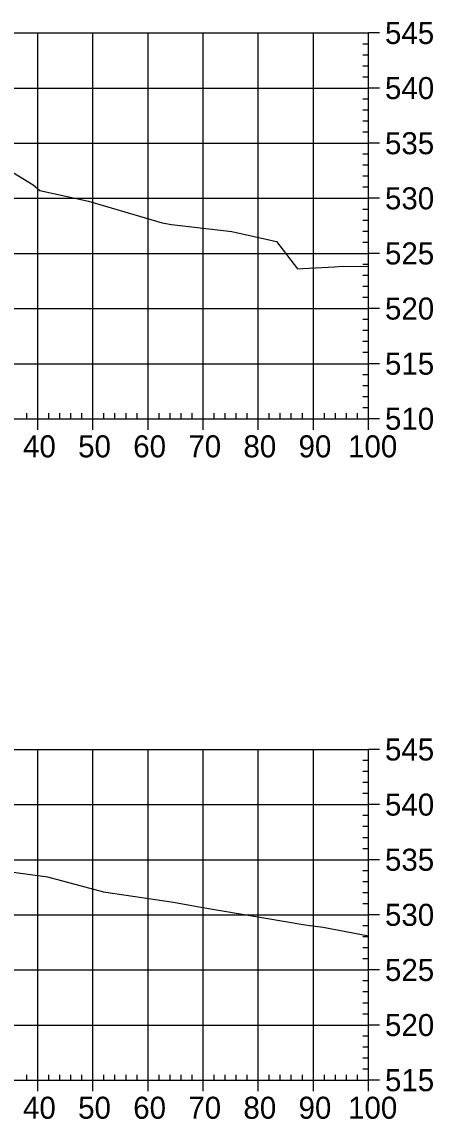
# Model space of a CAD drawing. Extents: x 704834 to 709892, y 372981 to 377533.
# Drawn here: x 707342 to 707416.6, y 376473.8 to 376672.8 of the extents above; entities that cross this region are included whole.
import ezdxf

# ---------------------------------------------------------------- set-up
doc = ezdxf.new("R2010")
doc.units = 0
doc.layers.add('57', color=7, linetype='Continuous')
doc.layers.add('Existing', color=7, linetype='Continuous')

msp = doc.modelspace()

# ---------------------------------------------------------------- linework, layer by layer
at = {"layer": '57'}
for p, q in [((707204.91, 376670.82), (707404.91, 376670.82)), ((707344.91, 376600.82), (707344.91, 376670.82)), ((707354.91, 376600.82), (707354.91, 376670.82)), ((707364.91, 376600.82), (707364.91, 376670.82)), ((707374.91, 376600.82), (707374.91, 376670.82)), ((707384.91, 376600.82), (707384.91, 376670.82)), ((707394.91, 376600.82), (707394.91, 376670.82)), ((707404.91, 376600.82), (707404.91, 376670.82)), ((707404.91, 376600.82), (707404.91, 376670.82)), ((707406.91, 376670.82), (707404.91, 376670.82)), ((707404.91, 376668.82), (707403.91, 376668.82)), ((707404.91, 376666.82), (707403.91, 376666.82)), ((707404.91, 376664.82), (707403.91, 376664.82)), ((707404.91, 376662.82), (707403.91, 376662.82)), ((707204.91, 376660.82), (707404.91, 376660.82)), ((707406.91, 376660.82), (707404.91, 376660.82)), ((707404.91, 376658.82), (707403.91, 376658.82)), ((707404.91, 376656.82), (707403.91, 376656.82)), ((707404.91, 376654.82), (707403.91, 376654.82)), ((707404.91, 376652.82), (707403.91, 376652.82)), ((707204.91, 376650.82), (707404.91, 376650.82)), ((707406.91, 376650.82), (707404.91, 376650.82)), ((707404.91, 376648.82), (707403.91, 376648.82)), ((707404.91, 376646.82), (707403.91, 376646.82)), ((707404.91, 376644.82), (707403.91, 376644.82)), ((707404.91, 376642.82), (707403.91, 376642.82)), ((707204.91, 376640.82), (707404.91, 376640.82)), ((707406.91, 376640.82), (707404.91, 376640.82)), ((707404.91, 376638.82), (707403.91, 376638.82)), ((707404.91, 376636.82), (707403.91, 376636.82)), ((707404.91, 376634.82), (707403.91, 376634.82)), ((707404.91, 376632.82), (707403.91, 376632.82)), ((707204.91, 376630.82), (707404.91, 376630.82)), ((707406.91, 376630.82), (707404.91, 376630.82)), ((707404.91, 376628.82), (707403.91, 376628.82)), ((707404.91, 376626.82), (707403.91, 376626.82)), ((707404.91, 376624.82), (707403.91, 376624.82)), ((707404.91, 376622.82), (707403.91, 376622.82)), ((707204.91, 376620.82), (707404.91, 376620.82)), ((707406.91, 376620.82), (707404.91, 376620.82)), ((707404.91, 376618.82), (707403.91, 376618.82)), ((707404.91, 376616.82), (707403.91, 376616.82)), ((707404.91, 376614.82), (707403.91, 376614.82)), ((707404.91, 376612.82), (707403.91, 376612.82)), ((707204.91, 376610.82), (707404.91, 376610.82)), ((707406.91, 376610.82), (707404.91, 376610.82)), ((707404.91, 376608.82), (707403.91, 376608.82)), ((707404.91, 376606.82), (707403.91, 376606.82)), ((707404.91, 376604.82), (707403.91, 376604.82)), ((707342.91, 376600.82), (707342.91, 376601.82)), ((707346.91, 376600.82), (707346.91, 376601.82)), ((707348.91, 376600.82), (707348.91, 376601.82)), ((707350.91, 376600.82), (707350.91, 376601.82)), ((707352.91, 376600.82), (707352.91, 376601.82)), ((707356.91, 376600.82), (707356.91, 376601.82)), ((707358.91, 376600.82), (707358.91, 376601.82)), ((707360.91, 376600.82), (707360.91, 376601.82)), ((707362.91, 376600.82), (707362.91, 376601.82)), ((707366.91, 376600.82), (707366.91, 376601.82)), ((707368.91, 376600.82), (707368.91, 376601.82)), ((707370.91, 376600.82), (707370.91, 376601.82)), ((707372.91, 376600.82), (707372.91, 376601.82)), ((707376.91, 376600.82), (707376.91, 376601.82)), ((707378.91, 376600.82), (707378.91, 376601.82)), ((707380.91, 376600.82), (707380.91, 376601.82)), ((707382.91, 376600.82), (707382.91, 376601.82)), ((707386.91, 376600.82), (707386.91, 376601.82)), ((707388.91, 376600.82), (707388.91, 376601.82)), ((707390.91, 376600.82), (707390.91, 376601.82)), ((707392.91, 376600.82), (707392.91, 376601.82)), ((707396.91, 376600.82), (707396.91, 376601.82)), ((707398.91, 376600.82), (707398.91, 376601.82)), ((707400.91, 376600.82), (707400.91, 376601.82)), ((707402.91, 376600.82), (707402.91, 376601.82)), ((707404.91, 376602.82), (707403.91, 376602.82)), ((707204.91, 376600.82), (707404.91, 376600.82)), ((707204.91, 376600.82), (707404.91, 376600.82)), ((707344.91, 376598.82), (707344.91, 376600.82)), ((707354.91, 376598.82), (707354.91, 376600.82)), ((707364.91, 376598.82), (707364.91, 376600.82)), ((707374.91, 376598.82), (707374.91, 376600.82)), ((707384.91, 376598.82), (707384.91, 376600.82)), ((707394.91, 376598.82), (707394.91, 376600.82)), ((707404.91, 376598.82), (707404.91, 376600.82)), ((707406.91, 376600.82), (707404.91, 376600.82)), ((707204.91, 376540.82), (707404.91, 376540.82)), ((707344.91, 376480.82), (707344.91, 376540.82)), ((707354.91, 376480.82), (707354.91, 376540.82)), ((707364.91, 376480.82), (707364.91, 376540.82)), ((707374.91, 376480.82), (707374.91, 376540.82)), ((707384.91, 376480.82), (707384.91, 376540.82)), ((707394.91, 376480.82), (707394.91, 376540.82)), ((707404.91, 376480.82), (707404.91, 376540.82)), ((707404.91, 376480.82), (707404.91, 376540.82)), ((707406.91, 376540.82), (707404.91, 376540.82)), ((707404.91, 376538.82), (707403.91, 376538.82)), ((707404.91, 376536.82), (707403.91, 376536.82)), ((707404.91, 376534.82), (707403.91, 376534.82)), ((707404.91, 376532.82), (707403.91, 376532.82)), ((707204.91, 376530.82), (707404.91, 376530.82)), ((707406.91, 376530.82), (707404.91, 376530.82)), ((707404.91, 376528.82), (707403.91, 376528.82)), ((707404.91, 376526.82), (707403.91, 376526.82)), ((707404.91, 376524.82), (707403.91, 376524.82)), ((707404.91, 376522.82), (707403.91, 376522.82)), ((707204.91, 376520.82), (707404.91, 376520.82)), ((707406.91, 376520.82), (707404.91, 376520.82)), ((707404.91, 376518.82), (707403.91, 376518.82)), ((707404.91, 376516.82), (707403.91, 376516.82)), ((707404.91, 376514.82), (707403.91, 376514.82)), ((707404.91, 376512.82), (707403.91, 376512.82)), ((707204.91, 376510.82), (707404.91, 376510.82)), ((707406.91, 376510.82), (707404.91, 376510.82)), ((707404.91, 376508.82), (707403.91, 376508.82)), ((707404.91, 376506.82), (707403.91, 376506.82)), ((707404.91, 376504.82), (707403.91, 376504.82)), ((707404.91, 376502.82), (707403.91, 376502.82)), ((707204.91, 376500.82), (707404.91, 376500.82)), ((707406.91, 376500.82), (707404.91, 376500.82)), ((707404.91, 376498.82), (707403.91, 376498.82)), ((707404.91, 376496.82), (707403.91, 376496.82)), ((707404.91, 376494.82), (707403.91, 376494.82)), ((707404.91, 376492.82), (707403.91, 376492.82)), ((707204.91, 376490.82), (707404.91, 376490.82)), ((707406.91, 376490.82), (707404.91, 376490.82)), ((707404.91, 376488.82), (707403.91, 376488.82)), ((707404.91, 376486.82), (707403.91, 376486.82)), ((707404.91, 376484.82), (707403.91, 376484.82)), ((707404.91, 376482.82), (707403.91, 376482.82)), ((707204.91, 376480.82), (707404.91, 376480.82)), ((707204.91, 376480.82), (707404.91, 376480.82)), ((707342.91, 376480.82), (707342.91, 376481.82)), ((707344.91, 376478.82), (707344.91, 376480.82)), ((707346.91, 376480.82), (707346.91, 376481.82)), ((707348.91, 376480.82), (707348.91, 376481.82)), ((707350.91, 376480.82), (707350.91, 376481.82)), ((707352.91, 376480.82), (707352.91, 376481.82)), ((707354.91, 376478.82), (707354.91, 376480.82)), ((707356.91, 376480.82), (707356.91, 376481.82)), ((707358.91, 376480.82), (707358.91, 376481.82)), ((707360.91, 376480.82), (707360.91, 376481.82)), ((707362.91, 376480.82), (707362.91, 376481.82)), ((707364.91, 376478.82), (707364.91, 376480.82)), ((707366.91, 376480.82), (707366.91, 376481.82)), ((707368.91, 376480.82), (707368.91, 376481.82)), ((707370.91, 376480.82), (707370.91, 376481.82)), ((707372.91, 376480.82), (707372.91, 376481.82)), ((707374.91, 376478.82), (707374.91, 376480.82)), ((707376.91, 376480.82), (707376.91, 376481.82)), ((707378.91, 376480.82), (707378.91, 376481.82)), ((707380.91, 376480.82), (707380.91, 376481.82)), ((707382.91, 376480.82), (707382.91, 376481.82)), ((707384.91, 376478.82), (707384.91, 376480.82)), ((707386.91, 376480.82), (707386.91, 376481.82)), ((707388.91, 376480.82), (707388.91, 376481.82)), ((707390.91, 376480.82), (707390.91, 376481.82)), ((707392.91, 376480.82), (707392.91, 376481.82)), ((707394.91, 376478.82), (707394.91, 376480.82)), ((707396.91, 376480.82), (707396.91, 376481.82)), ((707398.91, 376480.82), (707398.91, 376481.82)), ((707400.91, 376480.82), (707400.91, 376481.82)), ((707402.91, 376480.82), (707402.91, 376481.82)), ((707404.91, 376478.82), (707404.91, 376480.82)), ((707406.91, 376480.82), (707404.91, 376480.82))]:
    msp.add_line(p, q, dxfattribs=at)
at = {"layer": 'Existing'}
for points in [[(707340.29, 376645.57), (707344.06, 376643.27), (707345.26, 376642.25), (707354.08, 376640.33), (707367.48, 376636.36), (707369.15, 376636.07), (707380.12, 376634.81), (707388.2, 376632.96), (707392.01, 376628.01), (707392.98, 376628.07), (707398.73, 376628.41), (707400.11, 376628.5), (707404.91, 376628.47)], [(707340.02, 376518.61), (707346.64, 376517.72), (707356.81, 376515.01), (707369.53, 376513.09), (707374.46, 376512.24), (707393.42, 376509.02), (707395.22, 376508.74), (707396.66, 376508.59), (707404.91, 376506.98)]]:
    msp.add_lwpolyline(points, dxfattribs=at)

# ---------------------------------------------------------------- texts
at = {"layer": '57'}
for s, p in [('545', (707407.91, 376668.82)), ('540', (707407.91, 376658.82)), ('535', (707407.91, 376648.82)), ('530', (707407.91, 376638.82)), ('525', (707407.91, 376628.82)), ('520', (707407.91, 376618.82)), ('515', (707407.91, 376608.82)), ('510', (707407.91, 376598.82)), ('40', (707342.22, 376593.82)), ('50', (707352.22, 376593.82)), ('60', (707362.22, 376593.82)), ('70', (707372.22, 376593.82)), ('80', (707382.22, 376593.82)), ('90', (707392.22, 376593.82)), ('100', (707401.21, 376593.82)), ('545', (707407.91, 376538.82)), ('540', (707407.91, 376528.82)), ('535', (707407.91, 376518.82)), ('530', (707407.91, 376508.82)), ('525', (707407.91, 376498.82)), ('520', (707407.91, 376488.82)), ('515', (707407.91, 376478.82)), ('40', (707342.22, 376473.82)), ('50', (707352.22, 376473.82)), ('60', (707362.22, 376473.82)), ('70', (707372.22, 376473.82)), ('80', (707382.22, 376473.82)), ('90', (707392.22, 376473.82)), ('100', (707401.21, 376473.82))]:
    msp.add_text(s, height=4, dxfattribs=at).set_placement(p)

doc.saveas('drawing.dxf')
